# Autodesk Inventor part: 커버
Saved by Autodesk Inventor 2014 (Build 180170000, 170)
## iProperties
Created: 2026-09
Part Number: 커버
Material: 일반
Document SubType Name: Modeling
Designer: dg
Density: 1 g/cm^3
Appearance: 기본값
Author: dg
Author: jhkim
Creation Date: 2026-08-27
Sending System: Autodesk Inventor 2027
Preprocessor: ST-DEVELOPER v20.1
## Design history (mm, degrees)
node "커버1"
node "솔리드1"
node "기준1"
